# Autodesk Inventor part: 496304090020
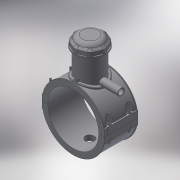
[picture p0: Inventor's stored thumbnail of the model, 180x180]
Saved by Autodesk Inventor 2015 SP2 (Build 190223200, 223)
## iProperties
Created: 2017-07
Part Number: 496304090020
Material: Generic
Description: PLASSON TAPPING SADDLE 90x20
Document SubType Name: Modeling
Designer: KIM
Mass: 571.454 g
Surface Area: 1449.71 cm^2
Volume: 571.454 cm^3
Density: 1 g/cm^3
Appearance: Default
Author: KIM
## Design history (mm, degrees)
derived "496304.ipt"
feature "Solid1::496304.ipt"
feature "Solid2::496304.ipt"
feature "Solid4::496304.ipt"
feature "Solid5::496304.ipt"
tag "TaggingFeature1"
body "Solid1"
body "Solid2"
other parameters: "d2" = 126, "d3" = 22.5, "d4" = 118, "d5" = 0, "d6" = 0.1, "d8" = 0, "d19" = 6, "d20" = 6, "d21" = 70.8, "d23" = 0, "d24" = 35.4, "d26" = 0, "d29" = 3, "d31" = 6, "d32" = 0, "d33" = 0, "d34" = 0.6, "d40" = 58.032, "d41" = 63, "d43" = 0, "d45" = 0, "d47" = 126.6, "d70" = 15, "d72" = 0, "d73" = 6, "d75" = 5, "d76" = 0, "d77" = 4.5, "d78" = 75, "d79" = 15, "d80" = 47.2, "d82" = 5 deg, "d84" = 4, "d85" = 14, "d86" = 0, "d87" = 3, "d88" = 0, "d89" = 1, "d90" = 1, "d91" = 94.4, "d92" = 0, "d93" = 0.5, "d94" = 47.36842, "d96" = 113.832, "d97" = 2.36, "d98" = 0, "d102" = 0.9, "d120" = 140 deg, "d121" = 24.228, "d122" = 20 deg, "d123" = 223.2, "d124" = 66.96, "d126" = 0, "d143" = 92.7, "d145" = 16.61538, "d149" = 1.35, "d150" = 18.27692, "d153" = 118, "d154" = 0, "d156" = 55.8, "d157" = 160 deg, "d159" = 4.32, "d161" = 1.35, "d162" = 70.8, "d163" = 0, "d164" = 45, "d167" = 9, "d168" = 54.43902, "d170" = 3.375, "d172" = 0, "d173" = 1, "d175" = 45, "d176" = 20 deg, "d177" = 6.3, "d178" = 21.6, "d180" = 0, "d183" = 8.64, "d184" = 5.04, "d185" = 38.35, "d186" = 38.35, "d187" = 55.8, "d188" = 6.48, "d189" = 6.3, "d190" = 0, "d191" = 83.7, "d193" = 6.3, "d194" = 4.13, "d195" = 90 deg, "d197" = 0, "d199" = 0, "d200" = 10.8, "d202" = 0, "d203" = 114, "d204" = 59.85, "d205" = 44.1, "d206" = 53.55, "d207" = 85.5, "d208" = 88.92, "d209" = 106.02, "d210" = 54.18, "d211" = 63, "d212" = 50.4, "d213" = 5.4, "d216" = 0, "d217" = 9, "d218" = 9, "d219" = 1.8, "d224" = 0, "d230" = 5.4, "d233" = 6, "d236" = 63, "d237" = 35.4, "d238" = 6.02433, "d240" = 35.4, "d241" = 35.4, "d242" = 35.4, "d243" = 6, "d244" = 35.4, "d245" = 35.4, "d246" = 35.4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
